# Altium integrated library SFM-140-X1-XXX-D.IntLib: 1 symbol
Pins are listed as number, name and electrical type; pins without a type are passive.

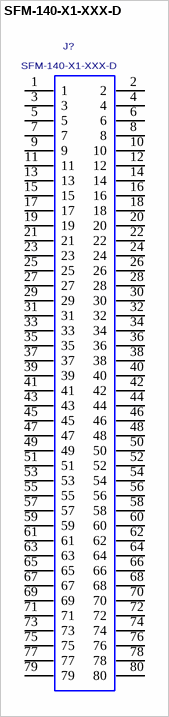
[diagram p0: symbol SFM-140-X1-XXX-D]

## SFM-140-X1-XXX-D
designator J?
SOCKET STRIP, .050" (1.27mm) PITCH, THRU-HOLE, 80 PINS.; MANUFACTURER: SAMTEC
footprint SFM-140-X1-XXX-D
pins: 1, 2, 3, 4, 5, 6, 7, 8, 9, 10, 11, 12, 13, 14, 15, 16, 17, 18, 19, 20, 21, 22, 23, 24, 25, 26, 27, 28, 29, 30, 31, 32, 33, 34, 35, 36, 37, 38, 39, 40, 41, 42, 43, 44, 45, 46, 47, 48, 49, 50, 51, 52, 53, 54, 55, 56, 57, 58, 59, 60, 61, 62, 63, 64, 65, 66, 67, 68, 69, 70, 71, 72, 73, 74, 75, 76, 77, 78, 79, 80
